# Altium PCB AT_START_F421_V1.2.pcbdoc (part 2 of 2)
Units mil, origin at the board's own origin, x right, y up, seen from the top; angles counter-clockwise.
Board outline 4706.37 x 3915.64 mil, 2 copper layers (Top Layer, Bottom Layer); 115 components, 101 nets, 469 pads, 319 vias.
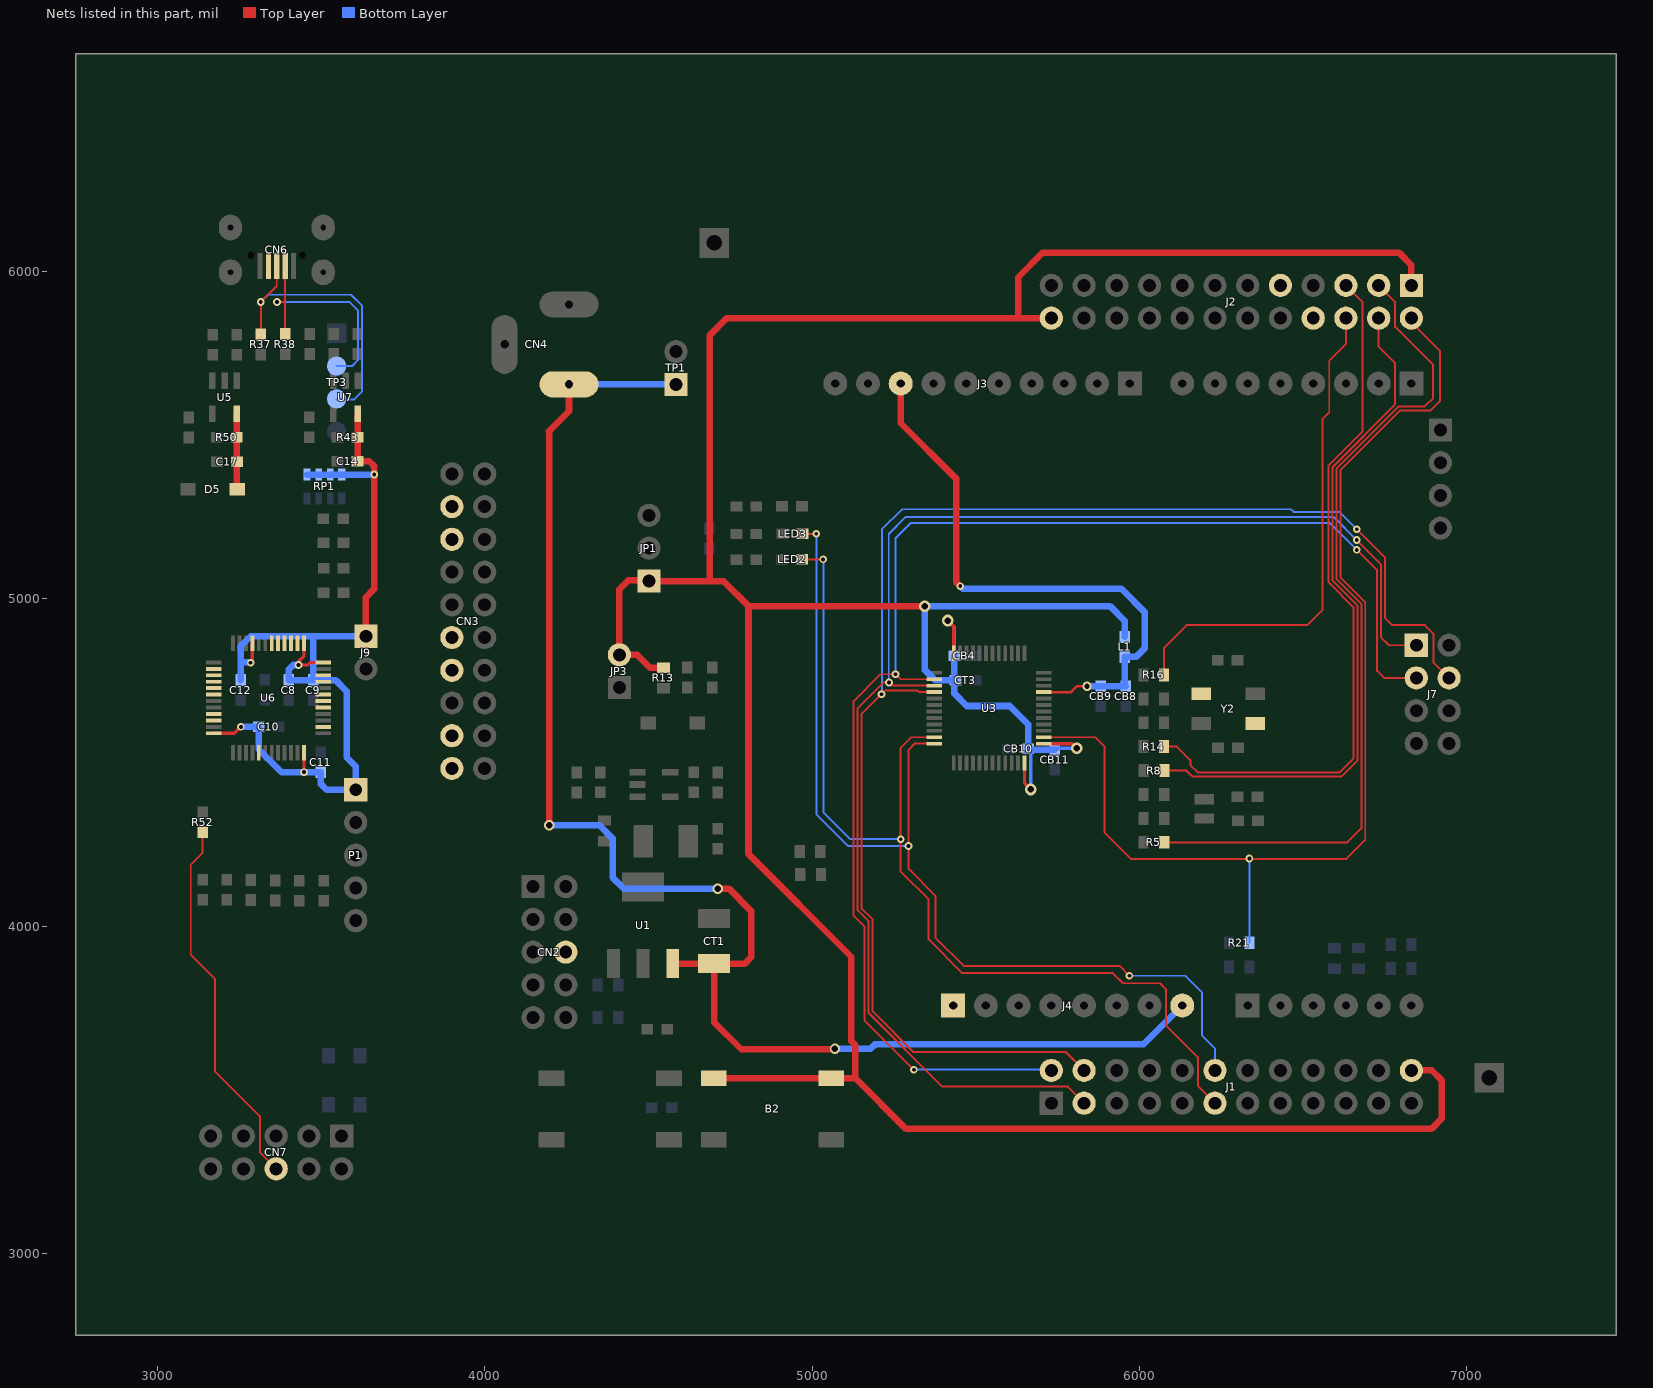
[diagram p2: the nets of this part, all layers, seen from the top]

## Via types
v1: diameter 23.62, hole 11.81, Top Layer to Bottom Layer, 298 vias
v2: diameter 35.43, hole 19.68, Top Layer to Bottom Layer, 11 vias
v3: diameter 31.5, hole 19.68, Top Layer to Bottom Layer, 8 vias
v4: diameter 27.56, hole 15.75, Top Layer to Bottom Layer, 2 vias

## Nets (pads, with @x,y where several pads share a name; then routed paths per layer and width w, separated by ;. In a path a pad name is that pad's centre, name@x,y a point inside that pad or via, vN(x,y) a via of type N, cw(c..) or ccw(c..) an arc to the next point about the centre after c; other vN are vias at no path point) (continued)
PB13: J1.2 J7.3 U3.26 | length 4312.9
  Top Layer w6: v1(5310.37,3561.94) 5160.37,3711.94 5160.37,3997.94 5126.37,4031.94 5126.37,4687.94 5208.37,4769.94 v1(5254.56,4769.94) 5269.86,4754.64 U3.26@5373.14,4754.64 ; v1(6663.37,5149.94) 6725.37,5087.94 6725.37,4780.09 6746.95,4758.51 J7.3@6845.37,4758.51
  Bottom Layer w6: v1(5254.56,4769.94) 5254.56,5186.13 5300.37,5231.94 6581.37,5231.94 v1(6663.37,5149.94) ; v1(5310.37,3561.94) 5728.8,3561.94 J1.2@5730.8,3559.94
PB14: J1.3 J7.1 U3.27 | length 4368.8
  Top Layer w6: U3.27@5373.14,4734.96 5244.35,4734.96 v1(5234.37,4744.94) 5217.94,4744.94 5138.37,4665.37 5138.37,4048.94 5172.37,4014.94 5172.37,3735.12 5397.55,3509.94 5780.8,3509.94 J1.3@5830.8,3459.94 ; v1(6663.37,5179.94) 6737.37,5105.94 6737.37,4883.09 6761.95,4858.51 J7.1@6845.37,4858.51
  Bottom Layer w6: v1(5234.37,4744.94) 5233.75,4745.56 5233.75,5198.32 5286.37,5250.94 6592.37,5250.94 v1(6663.37,5179.94)
PB15: J1.4 J7.4 U3.28 | length 4533.3
  Top Layer w6: U3.28@5373.14,4715.27 5327.04,4715.27 5321.37,4720.94 5223.37,4720.94 v1(5211.37,4708.94) 5150.37,4647.94 5150.37,4055.2 5184.37,4021.2 5184.37,3740.09 5308.52,3615.94 5774.8,3615.94 J1.4@5830.8,3559.94 ; v1(6663.37,5212.94) 6749.37,5126.94 6749.37,4943.09 6772.37,4920.09 6871.37,4920.09 6897.37,4894.09 6897.37,4806.51 J7.4@6945.37,4758.51
  Bottom Layer w6: v1(5211.37,4708.94) 5213.37,4710.94 5213.37,5110.89 5212.94,5111.32 5212.94,5212.51 5274.37,5273.94 6462.44,5273.94 6470.44,5265.94 6610.37,5265.94 v1(6663.37,5212.94)
PC13: J2.2 R21.2 U3.2 | length 3411.9
  Top Layer w6: U3.2@5707.79,4577.48 5864.37,4577.48 5892.37,4549.48 5892.37,4286.94 5973.37,4205.94 6631.22,4205.94 6689.37,4264.09 6689.37,4990 6613.37,5066 6613.37,5393.09 6796.37,5576.09 6889.37,5576.09 6917.37,5604.09 6917.37,5758.09 6829.95,5845.51 J2.2@6829.95,5857.24
  Bottom Layer w6: v1(6335.37,4206.94) 6335.84,4206.47 R21.2@6335.84,3949.86
PC14: J2.3 R5.2 | length 2547.6
  Top Layer w6: R5.2@6074.9,4256.58 6635.01,4256.58 6677.37,4298.94 6677.37,4985.03 6601.37,5061.03 6601.37,5398.06 6791.4,5588.09 6871.13,5588.09 6896.37,5613.34 6896.37,5714.94 6780.37,5830.94 6780.37,5906.81 J2.3@6729.95,5957.24
PC15: J2.4 R8.2 | length 2100.5
  Top Layer w6: R8.2@6074.9,4475.58 6143.33,4475.58 6161.02,4457.89 6617.32,4457.89 6665.37,4505.94 6665.37,4980.06 6589.37,5056.06 6589.37,5403.03 6780.37,5594.03 6780.37,5720.09 6729.95,5770.51 J2.4@6729.95,5857.24
PF0: J2.5 R14.2 | length 2178.9
  Top Layer w6: R14.2@6074.86,4548.79 6114.15,4548.79 6155.14,4507.8 6155.14,4492.17 6177.42,4469.89 6611.32,4469.89 6653.37,4511.94 6653.37,4975.09 6577.37,5051.09 6577.37,5408 6681.37,5512 6681.37,5905.81 J2.5@6629.95,5957.24
PF1: J2.6 R16.2 | length 1536.1
  Top Layer w6: R16.2@6074.43,4768.22 R16.2@6074.86,4767.79 6074.86,4851.42 6143.52,4920.09 6512.52,4920.09 6558.37,4965.94 6558.37,5549.09 6579.37,5570.09 6579.37,5727.51 6629.95,5778.09 J2.6@6629.95,5857.24
PF6: J1.11 LED2.2 U3.35 | length 3042.2
  Top Layer w6: LED2.2@4969.42,5120.5 4969.86,5120.94 v1(5033.37,5120.94) ; U3.35@5373.14,4577.48 5302.91,4577.48 5270.37,4544.94 v1(5270.37,4265.94) 5270.37,4166.94 5355.37,4081.94 5355.37,3959.94 5458.37,3856.94 5918.37,3856.94 5949.37,3825.94 6062.37,3825.94 6080.37,3807.94 6080.37,3697.7 6179.14,3598.94 6179.14,3511.6 J1.11@6230.8,3459.94
  Bottom Layer w6: v1(5033.37,5120.94) 5034.37,5119.94 5034.37,4347.94 5116.37,4265.94 v1(5270.37,4265.94)
PF7: J1.12 LED3.2 U3.36 | length 3054
  Top Layer w6: LED3.2@4970.57,5198.5 5011.93,5198.5 v1(5012.37,5198.94) ; U3.36@5373.14,4557.79 5373.14,4558.55 5313.99,4558.55 5294.37,4538.94 v1(5294.37,4244.94) 5294.37,4175.15 5376.37,4093.15 5376.37,3965.09 5462.52,3878.94 5938.79,3878.94 v1(5968.79,3848.94)
  Bottom Layer w6: v1(5012.37,5198.94) 5012.37,4342.94 5110.18,4245.13 5294.18,4245.13 v1(5294.37,4244.94) ; v1(5968.79,3848.94) 6139.37,3848.94 6190.37,3797.94 6190.37,3666.97 6230.8,3626.54 J1.12@6230.8,3559.94
SWO: CN7.6 R52.1 | length 1150.8
  Top Layer w6: R52.1@3137.55,4286.94 3137.55,4224.55 3101.61,4188.62 3101.61,3913.06 3175.55,3839.12 3175.55,3556.65 3312.43,3419.77 3312.43,3309.26 CN7.6@3362.55,3259.15
USBM: CN6.2 R38.1 TP3.2 | length 715.5
  Top Layer w6: v1(3365.13,5907.15) 3389.91,5907.15 ; R38.1@3389.4,5809.15 3389.91,5809.66 3389.91,5907.15 ; CN6.2@3390.06,6017.38 3389.91,6017.23 3389.91,5907.15
  Bottom Layer w6: v1(3365.13,5907.15) 3586.13,5907.15 3612.13,5881.15 3612.13,5729.15 3594.13,5711.15 TP3.2@3547.13,5711.15
USBP: CN6.3 R37.1 TP3.3 | length 910.9
  Top Layer w6: R37.1@3315.55,5808.04 v1(3315.55,5907.15) 3364.32,5955.92 3364.32,6017.23 CN6.3@3364.47,6017.38
  Bottom Layer w6: v1(3315.55,5907.15) 3337.55,5929.15 3591.13,5929.15 3625.13,5895.15 3625.13,5634.15 3602.13,5611.15 ; TP3.3@3547.13,5609.07 3602.13,5609.07
VCC: C8.2 C9.2 C10.2 C11.2 C12.2 C14.1 J9.1 P1.1 R43.2 RP1.5 RP1.6 RP1.7 RP1.8 U6.1 U6.9 U6.24 U6.36 U6.48 U7.5 | length 3028.5
  Top Layer w10: U6.24@3171.7,4589.56 3234.86,4589.56 v1(3254.55,4609.24) ; v1(3284.55,4805.15) 3289.81,4810.41 U6.9@3289.81,4865.15 ; v1@3447.29,4470.94 U6.36@3447.29,4530.5 ; U6.1@3447.29,4865.15 3447.29,4824.89 3430.55,4808.15 v1(3430.55,4798.15) 3459.55,4798.15 3467.49,4806.09 U6.48@3506.34,4806.09
  Top Layer w20: U7.5@3611.55,5565.96 3611.55,5421.25 C14.1@3611.17,5420.87 3647.06,5420.87 3661.55,5406.38 3661.55,5030.15 3636.55,5005.15 J9.1@3636.55,4886.15
  Bottom Layer w20: v1(3254.55,4609.24) C10.2@3309.49,4609.24 3309.49,4540.2 3378.93,4470.76 v1(3447.47,4470.76) C11.2@3499,4470.76 ; C12.2@3254.55,4752.15 3254.55,4806.15 ; v1(3284.55,4805.15) 3283.55,4806.15 3254.55,4806.15 ; v1(3430.55,4798.15) 3414.55,4798.15 3401.55,4785.15 C8.2@3401.55,4752.15 C9.2@3475.55,4752.15 ; RP1.8@3456.63,5379.86 RP1.7@3492.07,5379.86 RP1.6@3527.5,5379.86 RP1.5@3562.93,5379.86 v1(3662.07,5379.86) ; C11.2@3499.13,4470.89 3499.13,4434.65 3516.63,4417.15 P1.1@3605.55,4417.15 3605.55,4488.15 3577.55,4516.15 3577.55,4718.15 3543.55,4752.15 C9.2@3475.55,4752.15 ; J9.1@3636.55,4886.15 3475.55,4886.15 ; 3254.55,4806.15 3254.55,4856.15 3284.55,4886.15 3475.55,4886.15 ; C9.2@3475.55,4752.15 3475.55,4886.15
VCC3.5V: C17.1 D5.1 R50.2 U5.5 | length 231.2
  Top Layer w20: U5.5@3242.34,5566.04 3242.34,5335.93 D5.1@3243.13,5335.15
VDD: B2.1 CB4.1 CB10.1 CB11.1 CT3.1 J1.24 J2.1 J2.24 JP1.1 JP3.2 L1.1 R13.2 U3.1 U3.24 U3.48 | length 10805.7
  Top Layer w10: v2(5414.37,4933.94) 5432.2,4916.11 U3.24@5432.2,4833.38 ; U3.48@5648.73,4498.74 5648.73,4436.58 v2(5667.37,4417.94) ; U3.1@5707.79,4557.79 5794.52,4557.79 v2(5808.37,4543.94)
  Top Layer w20: JP1.1@4501.37,5055.09 JP1.1@4500.37,5054.09 ; 4504.01,4790.2 4464.97,4829.24 JP3.2@4410.97,4829.24 4410.97,5029.54 4438.37,5056.94 4466.52,5056.94 4469.37,5054.09 JP1.1@4500.37,5054.09 ; 4504.23,4789.98 R13.2@4545.69,4789.98 ; B2.1@4699.37,3535.9 B2.1@5058.37,3535.9 5132,3535.9 ; v2(5344.22,4978.09) 4805.37,4978.09 ; J2.24@5729.95,5857.24 5629.37,5857.24 ; J2.1@6829.95,5957.24 6829.95,6020.36 6792.37,6057.94 5704.37,6057.94 5629.37,5982.94 5629.37,5857.24 ; J1.24@6830.8,3559.94 6892.52,3559.94 6922.37,3530.09 6922.37,3412.09 6891.37,3381.09 5286.82,3381.09 5132,3535.9 ; JP1.1@4500.37,5054.09 4686.37,5054.09 ; 4686.37,5054.09 4729.37,5054.09 4805.37,4978.09 ; 4686.37,5054.09 4686.37,5805.09 4738.52,5857.24 5629.37,5857.24 ; 4805.37,4978.09 4805.37,4221.09 5119.37,3907.09 5119.37,3649.26 5132,3636.63 5132,3535.9
  Bottom Layer w10: v2(5414.37,4933.94) 5434.37,4913.94 CB4.1@5434.37,4826.94 ; v2(5667.37,4417.94) CB10.1@5667.37,4533.94 ; CB11.1@5741.37,4538.94 5746.37,4543.94 v2(5808.37,4543.94)
  Bottom Layer w20: CB4.1@5434.37,4826.94 CT3.1@5434.37,4751.94 ; CT3.1@5437.37,4751.94 CT3.1@5434.37,4751.94 ; CB11.1@5741.37,4538.94 5672.37,4538.94 5667.37,4533.94 CB10.1@5659.37,4541.94 5659.37,4616.94 5603.37,4672.94 5472.37,4672.94 5434.37,4710.94 CT3.1@5434.37,4751.94 ; L1.1@5954.37,4883.94 5954.37,4932.94 5909.22,4978.09 v2(5344.22,4978.09) 5344.22,4782.94 5375.22,4751.94 CT3.1@5434.37,4751.94
VDDA: CB8.1 CB9.1 J3.8 L1.2 U3.9 | length 1821.9
  Top Layer w8: U3.9@5707.79,4715.27 5791.05,4715.27 5809.02,4733.24 v4(5839.1,4733.24)
  Top Layer w20: J3.8@5270.37,5657.94 5270.37,5536.94 5439.37,5367.94 5439.37,5051.94 v1(5452.37,5038.94)
  Bottom Layer w20: v1(5452.37,5038.94) 5460.37,5030.94 5944.37,5030.94 6016.37,4958.94 6016.37,4849.94 5989.37,4822.94 L1.2@5954.37,4822.94 5954.37,4736.33 5957.42,4733.28 CB8.1@5957.26,4733.28 ; v4(5839.1,4733.24) 5881.6,4733.24 CB8.1@5957.46,4733.24
VIN: CN4.1 CT1.1 J4.8 TP1.1 U1.3 | length 4581.7
  Top Layer w20: v3(4197.08,4309.09) 4197.08,5510.69 4195.77,5512 4257.08,5573.3 CN4.1@4257.08,5655.42 ; U1.3@4573.92,3885.96 4700.25,3885.96 CT1.1@4700.37,3886.09 ; v3(4711.37,4115.09) 4745.37,4115.09 4813.37,4047.09 4813.37,3905.09 4794.37,3886.09 CT1.1@4700.37,3886.09 ; v3(5069.37,3626.09) 5067.37,3624.09 4783.37,3624.09 4700.37,3707.09 CT1.1@4700.37,3886.09
  Bottom Layer w20: v3(4197.08,4309.09) 4349.37,4309.09 4390.15,4268.31 4390.15,4149.31 4424.37,4115.09 v3(4711.37,4115.09) ; CN4.1@4257.08,5655.42 TP1.1@4583.83,5655.42 ; v3(5069.37,3626.09) 5178.37,3626.09 5191.37,3639.09 6011.52,3639.09 J4.8@6130.37,3757.94
"": CN2.6 CN3.3 CN3.5 CN3.11 CN3.13 CN3.17 CN3.19 CN6.4 CN6.MH1 CN6.MH2 J2.8 J2.9 J4.1 U6.2 U6.3 U6.4 U6.5 U6.6 U6.14 U6.15 U6.16 U6.17 U6.18 U6.21 U6.22 U6.29 U6.38 U6.41 U6.42 U6.43 U6.45 U6.46 Y2.2 Y2.4

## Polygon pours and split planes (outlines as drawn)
GND on Top Layer (solid, remove dead copper, pour order 0): 3747.58,3197.57 3078.19,3197.57 cw(c3078.19,3275.35) 3000.42,3275.35 3000.42,6136.49 cw(c3082.71,6136.49) 3082.71,6218.79 7127.67,6218.79 cw(c7127.67,6140.09) 7206.37,6140.09 7206.37,3271.1 cw(c7132.86,3271.1) 7132.86,3197.59
GND on Bottom Layer (solid, remove dead copper, pour order 1): 3747.58,3197.57 3078.19,3197.57 cw(c3078.19,3275.35) 3000.42,3275.35 3000.42,6136.49 cw(c3082.71,6136.49) 3082.71,6218.79 7127.67,6218.79 cw(c7127.67,6140.09) 7206.37,6140.09 7206.37,3271.1 cw(c7132.86,3271.1) 7132.86,3197.59

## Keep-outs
Board Outline Layer:
  circle w8 net "": c7082.37,6094.79 r62.99
  circle w8 net "": c7082.37,3320.1 r62.99
  circle w8 net "": c3891.39,6094.79 r62.99
  circle w8 net "": c3891.37,3320.1 r62.99
  circle w8 net "": c4880.37,3757.94 r62.99
  circle w8 net "": c6930.37,5057.94 r62.99
  circle w8 net "": c4930.37,5657.94 r62.99
  lines w8 net "": 3000.42,3275.35 3000,6160.4 cw(c3058.37,6160.41) 3058.37,6218.78 3082.71,6218.78 ; 3000.68,3275.35 ccw(c3079.42,3275.35) 3079.42,3196.61 ; 3649.37,6218.79 cw(c3649.37,6140.05) 3728.11,6140.05 3728.11,5823.39 ; 3649.76,3197.67 ccw(c3649.76,3276.41) 3728.5,3276.41 ; 3727.68,3726.18 3767.2,3726.18 ; 3727.68,3797.54 3767.2,3797.54 ; 3727.68,5094.61 3767.2,5094.61 ; 3727.81,3891.14 3767.33,3891.14 ; 3727.81,4000.62 3767.33,4000.62 ; 3727.81,5018.1 3767.33,5018.1 ; 3728.09,5746.33 3767.6,5746.33 ; 3728.37,3275.65 3728.37,3725.33 ; 3728.37,3798.39 3728.37,3890.39 ; 3728.37,4001.39 3728.37,5017.39 ; 3728.37,5095.39 3728.37,5745.39 ; 3728.94,5822.51 3768.46,5822.51 ; 3767.37,3275.59 3767.37,3725.33 ; 3767.33,3276.53 ccw(c3846.28,3276.53) 3846.28,3197.57 ; 3767.37,3798.39 3767.37,3890.39 ; 3767.37,4001.39 3767.37,5017.39 ; 3767.37,5095.39 3767.37,5745.39 ; 3767.63,5823.39 3767.63,6148.6 ; 3767.63,6140.05 cw(c3846.37,6140.05) 3846.37,6218.79 ; 7120.37,3197.59 7120.37,3000 6567.11,3000 3082.08,3000 3082.08,3197.59 6567.11,3197.59 7132.86,3197.59 ccw(c7132.86,3271.1) 7206.37,3271.1 ; 7120.37,6218.79 7120.37,6415.64 6566.21,6415.64 3082.71,6415.64 3082.71,6218.78 ; 7127.63,6218.79 6566.21,6218.79 3082.71,6218.79 ; 7127.63,6218.83 cw(c7127.63,6140.09) 7206.37,6140.09 7206.37,3269.94

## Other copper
Top Layer:
  drawing of 448 lines, arcs and shapes, not listed
Bottom Layer:
  region net $1N806: 3256.55,5651.15 3481.55,5651.15 3481.55,5683.15 3256.55,5683.15
  region net 3V3: 5520.37,3740.09 cw(c5420.37,3740.09) 5500.37,3680.09 5560.37,3680.09 cw(c5640.37,3740.09) 5540.37,3740.09
  region net ATLINK_5V: 3434.75,5879.15 3419.75,5849.15 ccw(c3419.75,5951.4) 3449.75,5853.65 3454.04,5874.65 ccw(c3434.75,5835.56)
  region net VCC: 3485.55,4816.15 cw(c3585.55,4816.15) 3505.55,4876.15 3445.55,4876.15 cw(c3365.55,4816.15) 3465.55,4816.15
  region net PB9: 6778.37,3674.39 6778.34,3673.63 6778.25,3672.82 6777.9,3671.07 6777.36,3669.22 6776.66,3667.34 6775.83,3665.52 6774.9,3663.83 6773.91,3662.35 6773.4,3661.71 6772.89,3661.15 6777.13,3656.91 6779.25,3663.27 6784.37,3674.39
  region net BOOT0: 4334.97,4024.2 4334.41,4024.23 4333.85,4024.33 4333.3,4024.5 4332.77,4024.72 4332.25,4024.99 4331.75,4025.31 4331.29,4025.67 4330.85,4026.07 4330.44,4026.51 4330.08,4026.98 4329.76,4027.48 4329.49,4028 4329.27,4028.53 4329.11,4029.08 4329.01,4029.64 4328.97,4030.2 4322.97,4030.2 4322.94,4029.64 4322.84,4029.08 4322.68,4028.53 4322.46,4028 4322.18,4027.48 4321.86,4026.98 4321.5,4026.51 4321.1,4026.07 4320.66,4025.67 4320.19,4025.31 4319.69,4024.99 4319.17,4024.72 4318.64,4024.5 4318.09,4024.33 4317.53,4024.23 4316.97,4024.2
  region net VDD: 5652.3,4534.87 5653.26,4533.83 5654.21,4532.64 5655.14,4531.31 5656.48,4529.13 5657.74,4526.75 5658.9,4524.23 5659.93,4521.64 5660.81,4519.03 5661.52,4516.46 5662.03,4514 5662.25,4512.44 5662.36,4510.97 5662.37,4510.28 5672.37,4510.28 5672.41,4511.37 5672.51,4512.44 5672.67,4513.47 5672.9,4514.48 5673.19,4515.45 5673.54,4516.39 5673.95,4517.31 5674.4,4518.19 5674.92,4519.03 5675.48,4519.85 5676.08,4520.63 5676.74,4521.38 5677.44,4522.1 5678.17,4522.78 5679.35,4523.74 5680.61,4524.63 5681.95,4525.43 5683.35,4526.15 5684.8,4526.8 5686.31,4527.36 5687.87,4527.84 5689.46,4528.23 5691.07,4528.54 5692.71,4528.76 5694.37,4528.89 5696.03,4528.94 5696.03,4548.94 5694.02,4548.87 5692.14,4548.69 5690.37,4548.41 5688.71,4548.05 5686.65,4547.48 5682.08,4545.9 5679.62,4545.06 5678.43,4544.74 5677.66,4544.57 5676.88,4544.44 5676.11,4544.37 5675.34,4544.35 5674.57,4544.4 5673.79,4544.51 5673,4544.7 5672.19,4544.96 5671.37,4545.31 5670.53,4545.75 5669.67,4546.29 5668.79,4546.93 5667.87,4547.68 5666.44,4549.01
  region net VDD: 5334.22,4958.09 5354.22,4948.09 ccw(c5286.06,4948.09) 5351.22,4968.09 5337.22,4970.95 ccw(c5363.28,4958.09)
  region net VDDA: 5480.37,5020.94 5484.51,5040.94 ccw(c5484.51,4991.27) 5467.51,5037.94 5467.51,5023.94 ccw(c5480.37,5050)
  region net 3V3: 3480,3742.94 3482.11,3742.87 3484.21,3742.68 3486.29,3742.36 3488.34,3741.92 3490.35,3741.35 3492.32,3740.68 3494.24,3739.88 3496.08,3738.98 3497.86,3737.97 3499.55,3736.86 3501.15,3735.65 3502.64,3734.34 3504.03,3732.93 3504.88,3731.94 3505.68,3730.91 3506.43,3729.84 3507.11,3728.74 3507.72,3727.6 3508.27,3726.42 3508.75,3725.2 3509.15,3723.96 3509.48,3722.67 3509.73,3721.36 3509.9,3720.01 3509.99,3718.64 3510,3717.94 3530,3717.94 3520,3747.94 3480,3772.94
  region net VDDA: 5911.26,4743.24 5911.26,4723.24 5941.26,4715.28 5941.26,4751.28
  region net VDDA: 5944.37,4781.28 5941.26,4751.28 5973.26,4751.28 5964.37,4781.28
  region net A5: 6843.84,3791.98 6797.5,3811.05 6791.88,3808.18 6794.91,3767.05
  region net A4: 6729.23,3794.54 6685.89,3801.81 6682.05,3797.17 6694.21,3752.23
  region net A3: 6632.67,3794.48 6588.48,3804.07 6584.24,3799.83 6593.83,3755.65
  region net A2: 6557.83,3782.16 6533.37,3820.18 6527.37,3820.18 6502.91,3782.16
  region net A1: 6466.92,3755.65 6476.51,3799.83 6472.27,3804.07 6428.08,3794.48
  region net A0: 6332.88,3803.55 6325.38,3794.55 6346.38,3794.55 6338.88,3803.55
  region net VIN: 4375.81,5665.42 4326.44,5690.42 4326.44,5620.42 4375.81,5645.42
  region net 3V3: 4025.95,5405.53 4009.37,5426.09 3989.37,5426.09 3972.8,5405.53
  region net PA13: 3897.15,5046.72 3939.84,5037.37 3944.09,5041.62 3934.74,5084.31
  region net PA14: 3897.15,4946.72 3939.84,4937.37 3944.09,4941.62 3934.74,4984.31
  region net NRST: 3897.15,4646.72 3939.84,4637.37 3944.09,4641.62 3934.74,4684.31
  region net PB13: 5708.81,3587.63 5670.37,3564.94 5669.95,3558.94 5705.17,3534.61
  region net PA15: 6333.57,3594.8 6290.66,3604.86 6286.3,3600.74 6294.96,3558.28
  region net PA14: 6333.19,3494.83 6290.36,3504.62 6286.05,3500.45 6294.98,3457.9
  region net PF7: 6257.23,3582.63 6233.8,3619.71 6227.8,3619.79 6204.08,3583.27
  region net PB8: 6765.73,3457.3 6775.09,3499.99 6770.84,3504.23 6728.15,3494.88
  region net PB9: 6757.23,3582.63 6733.8,3614.82 6727.8,3614.82 6704.08,3583.27
  region net PB2: 5895.01,5859.88 5885.66,5817.19 5889.9,5812.95 5932.59,5822.3
  region net A2: 6203.52,5834.55 6226.95,5808.52 6232.95,5808.52 6256.66,5833.91
  region net D0: 6265.74,5955.44 6275.09,5998.14 6270.84,6002.38 6228.15,5993.03
  region net A1: 6295.01,5959.88 6285.66,5917.19 6289.9,5912.95 6332.59,5922.3
  region net D1: 6327.55,5822.34 6370.38,5812.56 6374.7,5816.73 6365.77,5859.28
  region net D13: 6095.01,5959.88 6085.66,5917.19 6089.9,5912.95 6132.59,5922.3
  region net D12: 6096.99,5845.78 6095.09,5806.9 6101.15,5804.48 6146.33,5826.03
  region net D13: 5442.91,5633.72 5467.37,5608.94 5473.37,5608.94 5497.83,5633.72
  region net D13: 5497.83,5682.16 5473.37,5709.94 5467.37,5709.94 5442.91,5682.16
  region net D12: 5542.91,5633.72 5567.37,5595.69 5573.37,5595.69 5597.83,5633.72
  region net D12: 5597.83,5682.16 5573.37,5720.18 5567.37,5720.18 5542.91,5682.16
  region net D2: 6628.08,5621.4 6672.26,5611.8 6676.51,5616.05 6666.91,5660.23
  region net D1: 6757.83,5682.16 6733.37,5713.12 6727.37,5713.12 6702.91,5682.16
  region net D0: 6827.37,5703.55 6819.87,5694.55 6840.87,5694.55 6833.37,5703.55
  region net $3N595: 4597.93,3449.74 4588.93,3457.24 4588.93,3436.24 4597.93,3443.74
  region net $3N595: 4567.93,3470.09 4560.43,3461.09 4581.43,3461.09 4573.93,3470.09
  region net VDD: 5944.37,4931.94 5938.37,4901.94 5970.37,4901.94 5964.37,4931.94
  region net VDDA: 5944.37,4774.94 5964.37,4774.94 5970.37,4804.94 5938.37,4804.94
  region net VDDA: 5989.37,4832.94 5970.37,4840.94 5970.37,4804.94 5989.37,4812.94
  region net $2N484: 4524.05,5127.86 4561.52,5151.09 4561.69,5157.09 4525.55,5180.99
  region net 3V3: 6908.97,5581.52 6883.97,5551.52 6953.97,5551.52 6928.97,5581.52
  region net D2: 6895.53,5342.66 6858.73,5319.09 6858.73,5313.09 6895.53,5289.51
  region net 5V: 6943.15,4823.15 6980.9,4808.85 6995.04,4822.99 6980.74,4860.73
  region net NRST: 6810.01,4660.73 6800.66,4618.04 6804.9,4613.8 6847.59,4623.15
  region net ATLK_RX: 4211.82,3723.42 4202.47,3680.73 4206.71,3676.49 4249.41,3685.84
  region net ATLK_RX: 4270.88,3694.86 4307.45,3718.55 4307.39,3724.55 4270.36,3748
  region net ATLK_TX: 4211.82,3823.42 4202.47,3780.73 4206.71,3776.49 4249.41,3785.84
  region net ATLK_TX: 4270.55,3794.56 4307.41,3818.1 4307.43,3824.1 4270.7,3847.71
  region net NRST: 4123.75,3847.77 4086.95,3824.2 4086.95,3818.2 4123.75,3794.63
  region net PA14: 4144.97,3885.84 4187.66,3876.49 4191.9,3880.73 4182.55,3923.42
  region net PA14: 4123.75,3947.77 4086.95,3924.2 4086.95,3918.2 4123.75,3894.63
  region net BOOT0: 4270.62,3994.63 4307.42,4018.2 4307.42,4024.2 4270.62,4047.77
  region net PA13: 4144.97,3985.84 4187.66,3976.49 4191.9,3980.73 4182.55,4023.42
  region net PA13: 4123.75,4047.77 4086.95,4024.2 4086.95,4018.2 4123.75,3994.63
  region net 5V: 4273.76,4144.64 4257.19,4167.57 4237.19,4167.57 4220.61,4144.64
  region net $2N484: 4660.88,5157.09 4660.88,5151.09 4669.88,5143.59 4669.88,5164.59
  region net BOOT0: 4660.88,5218.05 4660.88,5212.05 4669.88,5204.55 4669.88,5225.55
  region net VCC: 3447.55,4762.15 3417.55,4770.15 3417.55,4734.15 3447.55,4742.15
  region net VCC: 3391.55,4785.15 3385.55,4770.15 3417.55,4770.15 3411.55,4785.15
  region net VCC: 3429.55,4762.15 3429.55,4742.15 3459.55,4734.15 3459.55,4770.15
  region net VCC: 3465.55,4800.15 3459.55,4770.15 3491.55,4770.15 3485.55,4800.15
  region net VCC: 3521.55,4762.15 3491.55,4770.15 3491.55,4734.15 3521.55,4742.15
  region net VCC: 3299.49,4563.24 3319.49,4563.24 3327.49,4593.24 3291.49,4593.24
  region net VCC: 3261.49,4619.24 3261.49,4599.24 3291.49,4593.24 3291.49,4625.24
  region net VCC: 3453.13,4480.76 3453.13,4460.76 3483.13,4452.89 3483.13,4488.89
  region net VCC: 3489.13,4434.65 3509.13,4434.65 3515.13,4452.89 3483.13,4452.89
  region net VCC: 3244.55,4800.15 3238.55,4770.15 3270.55,4770.15 3264.55,4800.15
  region net ATLK_TX: 3297.91,3256.93 3307.26,3299.62 3303.02,3303.86 3260.33,3294.51
  region net NRST: 3289.12,3382.58 3265.55,3419.38 3259.55,3419.38 3235.97,3382.58
  region net ATLINK_5V: 3585.98,3232.57 3615.85,3244.15 3615.85,3274.15 3585.98,3285.72
  region net 3V3: 3562.65,3424.58 3537.65,3394.58 3597.98,3394.58 3582.65,3424.58
  region net 3V3: 3512.07,3551.24 3532.07,3551.24 3541.75,3581.24 3502.38,3581.24
  region net 3V3: 3510,3658.48 3502.38,3628.48 3541.75,3628.48 3530,3658.48
  region net VCC: 3571.11,4896.15 3571.11,4876.15 3601.11,4851.15 3601.11,4921.15
  region net M-NRST: 3640.91,4114.93 3650.26,4157.62 3646.02,4161.86 3603.33,4152.51
  region net VCC: 3540.11,4427.15 3540.11,4407.15 3570.11,4382.15 3570.11,4452.15
  region net VCC: 3595.55,4482.58 3570.55,4452.58 3640.55,4452.58 3615.55,4482.58
  region net VCC: 3492.07,5389.86 3467.46,5398.56 3467.46,5361.16 3492.07,5369.86
  region net VCC: 3456.63,5389.86 3456.63,5369.86 3482.23,5361.16 3482.23,5398.56
  region net VCC: 3527.5,5389.86 3501.91,5398.56 3501.91,5361.16 3527.5,5369.86
  region net VCC: 3492.07,5389.86 3492.07,5369.86 3517.66,5361.16 3517.66,5398.56
  region net VCC: 3562.93,5389.86 3537.34,5398.56 3537.34,5361.16 3562.93,5369.86
  region net VCC: 3603.76,5389.86 3573.76,5398.56 3573.76,5361.16 3603.76,5369.86
  region net VCC: 3527.5,5389.86 3527.5,5369.86 3552.11,5361.16 3552.11,5398.56
  region net $1N792: 3453.63,5279.33 3459.63,5279.33 3467.13,5288.33 3446.13,5288.33
  region net $1N793: 3489.07,5279.33 3495.07,5279.33 3501.91,5288.33 3482.23,5288.33
  region net $1N794: 3524.5,5279.33 3530.5,5279.33 3537.34,5288.33 3517.66,5288.33
  region net $1N795: 3559.93,5279.33 3565.93,5279.33 3573.43,5288.33 3552.43,5288.33
  region net USBP: 3565.05,5587.68 3597.09,5606.07 3597.51,5612.07 3568.16,5631.87
  region net USBM: 3566.66,5689 3594.13,5708.15 3594.13,5714.15 3566.66,5733.29
  region net ATLINK_5V: 3484.13,5826.15 3484.13,5796.15 3517.6,5781.62 3517.6,5840.67
  region net M-NRST: 3325.05,4780.19 3317.55,4771.19 3338.55,4771.19 3331.05,4780.19
  region net 5V: 3613.16,3657.82 3598.86,3627.82 3638.23,3627.82 3633.16,3657.82
  region net ATLINK_5V: 3670.05,3423.91 3638.23,3477.82 3638.23,3430.58 3652.77,3398.76
  region net VDDA: 5839.1,4743.24 5839.1,4723.24 5865.6,4715.28 5865.6,4751.28
  region net VDDA: 5927.6,4743.24 5897.6,4751.28 5897.6,4715.28 5927.6,4723.24
  region net VDD: 5662.37,4510.94 5672.37,4510.94 5677.37,4525.94 5649.87,4525.94
  region net VDD: 5707.37,4548.94 5677.37,4557.94 5677.37,4525.94 5707.37,4528.94
  region net VDD: 5649.37,4587.94 5641.37,4557.94 5677.37,4557.94 5669.37,4587.94
  region net VDD: 5695.37,4548.94 5695.37,4528.94 5725.37,4520.94 5725.37,4556.94
  region net VDD: 5772.37,4548.94 5757.37,4556.94 5757.37,4526.44 5772.37,4538.94
  region net VDD: 5424.37,4710.94 5444.37,4710.94 5455.37,4735.94 5419.37,4735.94
  region net VDD: 5389.37,4761.94 5389.37,4741.94 5419.37,4735.94 5419.37,4767.94
  region net VDD: 5424.37,4797.94 5419.37,4767.94 5455.37,4767.94 5444.37,4797.94
  region net VDD: 5424.37,4780.94 5444.37,4780.94 5452.37,4810.94 5416.37,4810.94
  region net VDD: 5429.37,4857.94 5416.87,4842.94 5451.87,4842.94 5439.37,4857.94
  region net VIN: 4518.4,5665.42 4518.4,5645.42 4548.4,5620.42 4548.4,5690.42
  region net VIN: 6093.83,3760.23 6079.29,3721 6093.43,3706.85 6132.67,3721.4
  region net 5V: 5857.83,3782.16 5840.37,3809.94 5820.37,3809.94 5802.91,3782.16
  region net 3V3: 5702.91,3733.72 5720.37,3704.09 5740.37,3704.09 5757.83,3733.72
  region net 3V3: 5502.91,3733.72 5520.37,3695.69 5540.37,3695.69 5557.83,3733.72
  region net $3N595: 4625.28,3455.59 4613.02,3449.74 4613.02,3443.74 4625.28,3437.88
  region net 5V: 4290.41,4337.21 4306.76,4339.02 4306.76,4359.02 4290.41,4360.83
  region net 5V: 4748.19,4163.67 4731.83,4161.85 4731.83,4141.85 4748.19,4140.04
  region net NRST: 4574.16,3768.11 4578.69,3780.92 4574.45,3785.17 4561.63,3780.64
  region net VIN: 4700.96,4126.9 4684.6,4125.09 4684.6,4105.09 4700.96,4103.28
  region net VIN: 4207.49,4297.28 4223.85,4299.09 4223.85,4319.09 4207.49,4320.9
  region net VIN: 5079.79,3614.28 5096.14,3616.09 5096.14,3636.09 5079.79,3637.9
  region net 3V3: 5074.2,3659.05 5090.83,3660.09 5093.39,3680.09 5077.2,3682.48
  region net PA15: 6036.18,3890.23 6048.45,3896.09 6048.45,3902.09 6036.18,3907.95
  region net 3V3: 3506.71,3746.67 3510,3728.27 3530,3728.27 3533.29,3746.67
  region net $1N795: 3463.88,5009.29 3476.15,5015.15 3476.15,5021.15 3463.88,5027
  region net $1N794: 3463.88,5085 3476.15,5090.86 3476.15,5096.86 3463.88,5102.72
  region net $1N793: 3463.88,5162.19 3476.15,5168.05 3476.15,5174.05 3463.88,5179.91
  region net $1N792: 3465.63,5253.28 3459.63,5265.33 3453.63,5265.11 3447.93,5252.63
  region net M-NRST: 3333.88,4941 3346.15,4946.86 3346.15,4952.86 3333.88,4958.72
  region net M-NRST: 3319.44,4800.87 3325.05,4788.25 3331.05,4787.9 3337.13,4799.83
  region net M-USB_DM: 3350.73,4445 3338.47,4439.15 3338.47,4433.15 3350.73,4427.29
  region net M-USB_DP: 3350.73,4402 3338.47,4396.15 3338.47,4390.15 3350.73,4384.29
  region net USBP: 3327.33,5906.41 3331.87,5919.22 3327.62,5923.47 3314.81,5918.93
  region net USBM: 3372.94,5898.29 3385.2,5904.15 3385.2,5910.15 3372.94,5916
  region net M-USB_DM: 3355.34,5460.89 3350.81,5448.07 3355.05,5443.83 3367.87,5448.36
  region net M-USB_DP: 3322.34,5460.89 3317.81,5448.07 3322.05,5443.83 3334.87,5448.36
  region net VDDA: 5848.21,4722.91 5862.52,4723.24 5862.52,4743.24 5848.21,4743.58
  region net PB13: 5318.18,3553.08 5330.45,3558.94 5330.45,3564.94 5318.18,3570.8
  region net D8: 5223.11,3953.73 5210.29,3958.26 5206.05,3954.02 5210.58,3941.2
  region net PB9: 6649.88,3990.13 6655.74,3977.86 6661.74,3977.86 6667.59,3990.13
  region net $3N595: 6263.92,4032.84 6269.91,4020.77 6275.91,4020.96 6281.63,4033.42
  region net $3N595: 5834.5,4054.1 5840.37,4041.85 5846.37,4041.87 5852.22,4054.16
  region net PC13: 6326.83,4198.78 6332.84,4186.74 6338.84,4186.98 6344.53,4199.48
  region net A1: 6288.23,5599.75 6282.37,5612.02 6276.37,5612.02 6270.51,5599.75
  region net PB12: 5284.23,4803.75 5278.37,4816.02 5272.37,4816.02 5266.51,4803.75
  region net PB13: 5263.42,4777.75 5257.56,4790.02 5251.56,4790.02 5245.7,4777.75
  region net PB14: 5242.81,4753.21 5236.75,4765.17 5230.75,4764.85 5225.11,4752.27
  region net PB15: 5221.42,4715.14 5216.37,4728.45 5210.37,4729.48 5203.96,4718.14
  region net D2: 5251.56,4661.8 5239.29,4655.94 5239.29,4649.94 5251.56,4644.08
  region net PB6: 5076.63,4216.15 5089.45,4211.62 5093.69,4215.86 5089.16,4228.68
  region net PB6: 5527.56,4219.8 5515.29,4213.94 5515.29,4207.94 5527.56,4202.08
  region net D8: 5212.11,4646.73 5199.29,4651.26 5195.05,4647.02 5199.58,4634.2
  region net D5: 5463.56,4354.95 5451.29,4349.09 5451.29,4343.09 5463.56,4337.23
  region net A2: 6189.23,5593.75 6183.37,5606.02 6177.37,5606.02 6171.51,5593.75
  region net A3: 6030.56,5469 6018.29,5463.15 6018.29,5457.15 6030.56,5451.29
  region net A3: 6047.94,5453.23 6059.05,5459.75 6057.69,5465.75 6044.04,5470.51
  region net A2: 6168.8,5448.86 6157.7,5442.34 6159.05,5436.34 6172.7,5431.58
  region net A2: 6186.18,5433.08 6198.45,5438.94 6198.45,5444.94 6186.18,5450.8
  region net A1: 6287.18,5410.08 6299.45,5415.94 6299.45,5421.94 6287.18,5427.8
  region net PB9: 5616.47,4316.71 5604.26,4310.87 5604.32,4304.87 5616.65,4299
  region net PB9: 5616.56,4316.8 5604.29,4310.94 5604.29,4304.94 5616.56,4299.08
  region net D9: 5537.56,4340.8 5525.29,4334.94 5525.29,4328.94 5537.56,4323.08
  region net PB8: 5097.58,5407.68 5093.05,5394.86 5097.29,5390.62 5110.11,5395.15
  region net PB9: 5133.58,5409.68 5129.05,5396.86 5133.29,5392.62 5146.11,5397.15
  region net D5: 6320.87,5399.49 6309.44,5393.13 6310.37,5387.13 6323.59,5381.99
  region net D4: 6422.7,5379.92 6410.34,5374.13 6410.25,5368.13 6422.42,5362.21
  region net D3: 6519.29,5359.49 6507.87,5353.13 6508.8,5347.13 6522.01,5341.99
  region net D8: 6013.37,5344.8 6001.1,5338.94 6001.1,5332.94 6013.37,5327.08
  region net D8: 6024.71,5324.67 6039.68,5328.13 6042.36,5334.13 6031.93,5340.85
  region net D8: 6623.58,5359.68 6619.05,5346.86 6623.29,5342.62 6636.11,5347.15
  region net D2: 6665.17,5323.35 6653.83,5316.94 6654.86,5310.94 6668.17,5305.89
  region net NRST: 6485.18,5284.08 6497.45,5289.94 6497.45,5295.94 6485.18,5301.8
  region net NRST: 6645.11,5277.73 6632.29,5282.26 6628.05,5278.02 6632.58,5265.2
  region net PB15: 6664.11,5224.73 6651.29,5229.26 6647.05,5225.02 6651.58,5212.2
  region net PB14: 6664.11,5191.73 6651.29,5196.26 6647.05,5192.02 6651.58,5179.2
  region net PB12: 6665.11,5127.73 6652.29,5132.26 6648.05,5128.02 6652.58,5115.2
  region net PB11: 5528.84,5191.1 5517.05,5184.94 5517.56,5178.94 5530.34,5173.45
  region net PB11: 5545.18,5174.08 5557.45,5179.94 5557.45,5185.94 5545.18,5191.8
  region net A3: 5650.75,5452 5663.95,5457.15 5664.87,5463.15 5653.44,5469.51
  region net A2: 5799.18,5430.08 5811.45,5435.94 5811.45,5441.94 5799.18,5447.8
  region net PB11: 6664.11,5093.73 6651.29,5098.26 6647.05,5094.02 6651.58,5081.2
  region net D7: 6118.58,5160.68 6114.05,5147.86 6118.29,5143.62 6131.11,5148.15
  region net A0: 6388.18,5016.08 6400.45,5021.94 6400.45,5027.94 6388.18,5033.8
  region net PB2: 5455.11,5573.73 5442.3,5578.26 5438.05,5574.02 5442.58,5561.2
  region net D9: 5840.56,5419.8 5828.29,5413.94 5828.29,5407.94 5840.56,5402.08
  region net D10: 5763.56,5502.8 5751.29,5496.94 5751.29,5490.94 5763.56,5485.08
  region net D13: 5724.34,5530.43 5711.56,5524.94 5711.05,5518.94 5722.84,5512.77
  region net D12: 5689.56,5554.8 5677.29,5548.94 5677.29,5542.94 5689.56,5537.08
  region net D12: 5705.18,5537.08 5717.45,5542.94 5717.45,5548.94 5705.18,5554.8
  region net PB1: 5628.18,5580.08 5640.45,5585.94 5640.45,5591.94 5628.18,5597.8
  region net NRST: 6789.23,4122.75 6783.37,4135.02 6777.37,4135.02 6771.51,4122.75
  region net NRST: 5868.21,4106.4 5874.37,4094.62 5880.37,4095.13 5885.86,4107.91
  region net PA14: 6002.84,3860.74 6015.98,3865.94 6016.85,3871.94 6005.37,3878.28
  region net PF7: 5976.6,3840.08 5988.87,3845.94 5988.87,3851.94 5976.6,3857.8
  region net PA15: 5415.56,4167.8 5403.29,4161.94 5403.29,4155.94 5415.56,4150.08
  region net PA15: 5086.91,4149.77 5098.69,4155.94 5098.18,4161.94 5085.41,4167.43
  region net PA13: 5296.56,4015.8 5284.29,4009.94 5284.29,4003.94 5296.56,3998.08
  region net PA14: 5393.36,3992.35 5382.02,3985.94 5383.05,3979.94 5396.36,3974.89
  region net D2: 5246.11,3979.73 5237.35,3980.2 5233.11,3975.96 5233.58,3967.2
  region net NRST: 5371.56,3901.8 5359.29,3895.94 5359.29,3889.94 5371.56,3884.08
  region net NRST: 5387.18,3884.08 5399.45,3889.94 5399.45,3895.94 5387.18,3901.8
  region net 5V: 5011.79,3841.96 5012.37,3825.19 5032.37,3821.31 5034.98,3837.46
  region net 5V: 5036.52,3838.81 5052.77,3840.94 5051.5,3860.94 5035.02,3862.39
  region net PF6: 5262.56,4274.8 5250.29,4268.94 5250.29,4262.94 5262.56,4257.08
  region net PF7: 5286.7,4253.92 5274.34,4248.13 5274.25,4242.13 5286.42,4236.21
  region net D10: 5065.04,4365.56 5059.18,4377.83 5053.18,4377.83 5047.32,4365.56
  region net PF6: 5025.21,5112.4 5031.37,5100.62 5037.37,5101.13 5042.86,5113.9
  region net PF7: 5003.51,5191.13 5009.37,5178.86 5015.37,5178.86 5021.23,5191.13
  region net VDD: 5330.93,4966.37 5334.22,4947.97 5354.22,4947.97 5357.51,4966.37
  region net VDD: 5355.94,4964.8 5374.34,4968.09 5374.34,4988.09 5355.94,4991.38
  region net VDD: 5413.26,4916.26 5430.84,4910.4 5437.91,4917.47 5432.05,4935.05
  region net VDD: 5680.66,4429.66 5672.37,4448.06 5662.37,4448.06 5654.08,4429.66
  region net VDD: 5796.65,4557.23 5778.25,4548.94 5778.25,4538.94 5796.65,4530.65
  region net PB11: 5382.07,5173.13 5394.41,5178.94 5394.49,5184.94 5382.29,5190.85
  region net BOOT0: 5578.56,4055.8 5566.29,4049.94 5566.29,4043.94 5578.56,4038.08
  region net LD4: 3149.32,4529.73 3136.5,4534.26 3132.26,4530.02 3136.79,4517.2
  region net LD4: 3119.69,4908.48 3125.55,4896.21 3131.55,4896.21 3137.4,4908.48
  region net ATLK_RX: 3461.56,3819.8 3449.29,3813.94 3449.29,3807.94 3461.56,3802.08
  region net ATLK_RX: 3477.18,3802.08 3489.45,3807.94 3489.45,3813.94 3477.18,3819.8
  region net NRST: 3320.36,3855.08 3332.63,3860.94 3332.63,3866.94 3320.36,3872.8
  region net BOOT0: 3293.36,3909.08 3305.63,3914.94 3305.63,3920.94 3293.36,3926.8
  region net D3: 5494.76,4406.8 5482.49,4400.94 5482.49,4394.94 5494.76,4389.08
  region net D4: 5439.26,4381.8 5426.99,4375.94 5426.99,4369.94 5439.26,4364.08
  region net D7: 5488.18,5133.08 5500.45,5138.94 5500.45,5144.94 5488.18,5150.8
  region net D6: 6218.58,5124.68 6218.25,5116.06 6222.49,5111.82 6231.11,5112.15
  region net D6: 5311.23,4703.4 5305.37,4715.67 5299.37,4715.67 5293.51,4703.4
  region net PB8: 5602.11,4281.73 5589.29,4286.26 5585.05,4282.02 5589.58,4269.2
  region net PA13: 3685.43,3872.41 3672.62,3876.94 3668.37,3872.69 3672.91,3859.88
  region net NRST: 3303.64,3618.28 3309.5,3606.01 3315.5,3606.01 3321.36,3618.28
  region net ATLK_RX: 3156.19,3802.17 3168.59,3807.94 3168.72,3813.94 3156.58,3819.88
  region net PA13: 3244.9,3941.48 3257.17,3947.34 3257.17,3953.34 3244.9,3959.2
  region net PA14: 3206.88,3884.08 3219.15,3889.94 3219.15,3895.94 3206.88,3901.8
  region net ATLK_TX: 3340,3618.28 3345.86,3606.01 3351.86,3606.01 3357.72,3618.28
  region net ATLK_TX: 3358.39,3828.09 3370.66,3833.94 3370.66,3839.94 3358.39,3845.8
  region net PA14: 3635.29,3815.73 3622.47,3820.26 3618.23,3816.02 3622.76,3803.2
  region net BOOT0: 3658.96,3841.88 3646.14,3846.41 3641.9,3842.17 3646.43,3829.35
  region net 5V: 4076.98,4178.61 4087.26,4191.45 4073.12,4205.59 4060.27,4195.31
  region net 5V: 3609.87,3708.75 3613.16,3690.35 3633.16,3690.35 3636.44,3708.75

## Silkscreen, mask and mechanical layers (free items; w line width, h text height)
Top Silkscreen Layer:
  drawing of 1269 lines, arcs and shapes, not listed
  text "23" at 5697.37,6122.94 h36
  text "11" at 6306.37,6122.09 h36
  text "1" at 6822.37,6122.09 h36
  text "B1" at 5925.37,6032.98 h40 r45
  text "A1" at 6324.79,6031.5 h40 r45
  text "F0" at 6619.13,6029.14 h40 r45
  text "NC" at 6422.07,6025.5 h40 r45
  text "A7" at 6017.43,6025.44 h40 r45
  text "A5" at 6124.06,6025.44 h40 r45
  text "A3" at 6222.62,6025.44 h40 r45
  text "NRST" at 6515.39,6025.44 h40 r45
  text "B10" at 5811.65,6018.54 h36 r45
  text "GND" at 5707.41,6016.42 h36 r45
  text "C14" at 6704.68,6014.4 h40 r45
  text "VDD" at 6801.68,6014.33 h40 r45
  text "GND" at 4647.6,5944.61 h48
  text "F1" at 6623.82,5725.19 h40 r45
  text "B2" at 5913.35,5716.91 h40 r45
  text "B0" at 6014.38,5716.91 h40 r45
  text "A6" at 6116.33,5716.1 h40 r45
  text "A4" at 6220.93,5714.75 h40 r45
  text "A2" at 6318.56,5715.42 h40 r45
  text "A0" at 6416.06,5715.42 h40 r45
  text "NC" at 6515.39,5715.49 h40 r45
  text "B11" at 5806.41,5712.6 h40 r45
  text "C15" at 6717.75,5707.46 h38 r45
  text "C13" at 6820.04,5707.46 h38 r45
  text "VDD" at 5696.19,5704.32 h40 r45
  text "VIN (7V-12V)" at 4513.05,5659.05 h48 r90
  text "4" at 6455.67,5548.09 h48 r90
  text "8" at 5994.67,5547.09 h48 r90
  text "7" at 6158.67,5547.09 h48 r90
  text "2" at 6652.67,5547.09 h48 r90
  text "13" at 5492.67,5506.09 h48 r90
  text "12" at 5592.67,5506.09 h48 r90
  text "#6" at 6254.67,5500.09 h48 r90
  text "#5" at 6355.67,5500.09 h48 r90
  text "#9" at 5893.67,5499.09 h48 r90
  text "#3" at 6554.67,5499.09 h48 r90
  text "#11" at 5692.67,5459.09 h48 r90
  text "#10" at 5793.67,5459.09 h48 r90
  text "SCL" at 5092.67,5449.09 h48 r90
  text "SDA" at 5192.67,5449.09 h48 r90
  text "GND" at 5393.37,5449.09 h48 r90
  text "DIGITAL(#=PWM)" at 5842.67,5405.09 h48
  text "TX 1" at 6755.67,5404.09 h48 r90
  text "RX 0" at 6856.67,5404.09 h48 r90
  text "VDDA" at 5293.37,5402.09 h48 r90
  text "LD:" at 3643.7,5363.05 h36 r270
  text "BOOT0" at 4398.37,5331.94 h48
  text "AT-Link-EZ V1.4" at 3044.13,5261.15 h60 r270
  text "1" at 3645.87,5246.75 h36 r270
  text "GND" at 4420.37,5208.73 h36 r90
  text "2" at 3644.87,5179.75 h36 r270
  text "3" at 3643.87,5106.75 h36 r270
  text "AT-START-F421 V1.2" at 5495.03,5091.94 h59.06
  text "4" at 3644.87,5031.75 h36 r270
  text "VDD" at 4420.37,5003.05 h36 r90
  text "MISO" at 6606.56,4837.17 h48
  text "5V" at 7020.08,4836.2 h48
  text "SCK" at 6647.23,4736.13 h48
  text "MOSI" at 7020.62,4735.99 h48
  text "IDD" at 4332.44,4721.13 h48 r90
  text "RESET" at 6551.01,4636.84 h48
  text "GND" at 7020.08,4635.77 h48
  text "NSS" at 6646.8,4536.68 h48
  text "PB11" at 7020.08,4536.1 h48
  text "20-pin ARM standard JTAG" at 4203.32,4371.09 h48 r90
  text "POWER" at 5933.24,3986.71 h48
  text "ANALOG IN" at 6449.39,3986.26 h48
  text "IOREF" at 5555.37,3832.94 h48 r90
  text "RESET" at 5655.37,3832.94 h48 r90
  text "3.3V" at 5753.37,3833.09 h48 r90
  text "5V" at 5853.37,3833.09 h48 r90
  text "VIN" at 6157.37,3832.94 h48 r90
  text "AN0" at 6350.37,3832.94 h48 r90
  text "AN1" at 6450.37,3832.94 h48 r90
  text "AN2" at 6551.37,3833.09 h48 r90
  text "AN3" at 6650.37,3832.94 h48 r90
  text "AN4" at 6750.37,3832.94 h48 r90
  text "AN5" at 6850.37,3832.94 h48 r90
  text "GND" at 5960.37,3825.94 h48 r90
  text "GND" at 6062.37,3825.94 h48 r90
  text "SWC" at 3336.69,3777.95 h42 r270
  text "GND" at 3145.37,3776.94 h42 r270
  text "SWD" at 3435.3,3776.8 h42 r270
  text "3V3" at 3541.93,3775.79 h42 r270
  text "NRST" at 3243.37,3773.94 h42 r270
  text "AT-Link" at 4024.47,3754.81 h48 r90
  text "GND" at 7008.14,3633.16 h48
  text "F7" at 6221.28,3628.57 h40 r45
  text "B6" at 6513.8,3627.02 h40 r45
  text "B9" at 6730.37,3627.02 h40 r45
  text "A9" at 5912.13,3625.54 h40 r45
  text "B4" at 6412.37,3625.67 h40 r45
  text "A11" at 6007.28,3620.55 h40 r45
  text "B13" at 5699.04,3619.98 h38 r40
  text "B15" at 5804.89,3619.98 h38 r40
  text "A13" at 6101.92,3618.7 h38 r40
  text "A15" at 6295.25,3618.7 h38 r40
  text "BOOT0" at 6577.21,3617.02 h30 r30
  text "VDD" at 6818.88,3613.75 h40 r45
  text "SWO" at 3342.42,3602.51 h42 r270
  text "BOOT0" at 3441.52,3602.51 h40 r270
  text "RX" at 3144.49,3601.53 h42 r270
  text "5V" at 3539.88,3600.55 h42 r270
  text "TX" at 3231.04,3599.56 h42 r270
  text "F6" at 6229.42,3315.08 h40 r45
  text "B3" at 6418.27,3312.19 h40 r45
  text "B5" at 6517.63,3312.19 h40 r45
  text "B7" at 6628.68,3312.19 h40 r45
  text "B8" at 6727.2,3312.19 h40 r45
  text "A8" at 5919.67,3310.7 h40 r45
  text "B12" at 5696.83,3301.82 h40 r45
  text "B14" at 5812.83,3301.14 h40 r45
  text "A10" at 6008.2,3300.34 h40 r45
  text "A12" at 6104.59,3300.34 h40 r45
  text "A14" at 6306.91,3299.66 h40 r45
  text "GND" at 6829.9,3298.11 h40 r45
  text "25" at 5688.37,3239.09 h36
  text "35" at 6200.37,3239.09 h36
  text "48" at 6797.37,3239.09 h36
  text "RESET" at 4268.17,3229.9 h48
  text "USER" at 4789.26,3229.9 h48
Bottom Silkscreen Layer:
  drawing of 295 lines, arcs and shapes, not listed
  text "23" at 5716.85,6029.09 h36 r315
  text "21" at 5816.85,6029.09 h36 r315
  text "19" at 5921.85,6029.09 h36 r315
  text "17" at 6012.85,6029.09 h36 r315
  text "15" at 6114.85,6029.09 h36 r315
  text "13" at 6221.85,6029.09 h36 r315
  text "NC" at 6410.85,6029.09 h36 r315
  text "7" at 6515.27,6029.09 h36 r315
  text "5" at 6614.27,6029.09 h36 r315
  text "3" at 6713.27,6029.09 h36 r315
  text "1" at 6808.27,6029.09 h36 r315
  text "11" at 6316.85,6028.09 h36 r315
  text "22" at 5809.85,5741.09 h36 r315
  text "20" at 5909.85,5741.09 h36 r315
  text "18" at 6004.85,5741.09 h36 r315
  text "16" at 6101.85,5741.09 h36 r315
  text "14" at 6203.85,5741.09 h36 r315
  text "12" at 6304.85,5741.09 h36 r315
  text "10" at 6407.85,5741.09 h36 r315
  text "NC" at 6501.85,5741.09 h36 r315
  text "6" at 6607.27,5741.09 h36 r315
  text "4" at 6703.27,5741.09 h36 r315
  text "2" at 6803.27,5741.09 h36 r315
  text "24" at 5703.85,5739.09 h36 r315
  text "VDD" at 6835.11,5497.27 h36
  text "AT32F421C8T7" at 6155.03,5417.94 h120
  text "USART1_TX" at 6815.94,5400.56 h36
  text "3V3" at 4178.32,5358.52 h36
  text "3V3" at 4320.28,5358.52 h36
  text "USART1_RX" at 6815.94,5300.34 h36
  text "NC" at 4168.39,5264.94 h36
  text "GND" at 4318.22,5262.94 h36
  text "GND" at 6835.11,5199.78 h36
  text "NC" at 4167.39,5162.94 h36
  text "GND" at 4320.38,5161.12 h36
  text "SWDIO" at 4214.9,5058.94 h36
  text "GND" at 4345.22,5058.94 h36
  text "GND" at 4345.22,4962.94 h36
  text "SWCLK" at 4221.9,4958.94 h36
  text "NC" at 4181.48,4863.09 h36
  text "GND" at 4320.02,4863.09 h36
  text "VDD" at 3521.5,4854.15 h36 r270
  text "NC" at 4181.48,4759.51 h36
  text "GND" at 4320.38,4760.09 h36
  text "NRST" at 4175.16,4666.39 h36
  text "GND" at 4320.28,4666.43 h36
  text "M-BOOT0" at 3520.5,4574.15 h36 r270
  text "NC" at 4181.48,4563.09 h36
  text "GND" at 4319.66,4563.09 h36
  text "NC" at 4181.48,4461.09 h36
  text "GND" at 4320.28,4461.09 h36
  text "VDD" at 3537.58,4376.22 h36
  text "M-SWDIO" at 3525.27,4298.86 h36
  text "M-SWCLK" at 3525.27,4198.86 h36
  text "3V3" at 4065.5,4103.27 h36
  text "E5V" at 4419.2,4102.91 h36
  text "M-NRST" at 3528.43,4098.86 h36
  text "SWDIO" at 4059.18,4002.98 h36
  text "BOOT0" at 4484.65,4002.98 h36
  text "GND" at 3537.92,3998.86 h36
  text "SWCLK" at 4059.18,3902.7 h36
  text "NC" at 4386.47,3902.7 h36
  text "NRST" at 4062.34,3802.76 h36
  text "USART1_RX" at 4740.25,3802.63 h36
  text "GND" at 4065.5,3703.18 h36
  text "USART1_TX" at 4740.25,3703.03 h36
  text "26" at 5722.85,3617.09 h36 r315
  text "28" at 5819.85,3617.09 h36 r315
  text "30" at 5924.85,3617.09 h36 r315
  text "32" at 6021.85,3617.09 h36 r315
  text "34" at 6121.85,3617.09 h36 r315
  text "36" at 6222.85,3617.09 h36 r315
  text "38" at 6322.85,3617.09 h36 r315
  text "40" at 6422.85,3617.09 h36 r315
  text "44" at 6628.85,3617.09 h36 r315
  text "46" at 6729.85,3617.09 h36 r315
  text "48" at 6830.85,3617.09 h36 r315
  text "42" at 6523.85,3616.09 h36 r315
  text "25" at 5717.85,3323.09 h36 r315
  text "27" at 5814.85,3323.09 h36 r315
  text "31" at 6019.85,3323.09 h36 r315
  text "35" at 6218.85,3323.09 h36 r315
  text "37" at 6318.85,3323.09 h36 r315
  text "39" at 6419.85,3323.09 h36 r315
  text "41" at 6517.85,3323.09 h36 r315
  text "43" at 6618.85,3323.09 h36 r315
  text "45" at 6727.85,3323.09 h36 r315
  text "47" at 6829.85,3323.09 h36 r315
  text "29" at 5921.85,3321.09 h36 r315
  text "33" at 6119.85,3321.09 h36 r315
Mechanical Layer:
  lines w1 net "": 3828.44,3319 cw(c3892.75,3319.01) 3892.05,3383.31 ; 3828.44,3319 3828.44,3319 ; 3828.44,3319 ccw(c3889.36,3318.9) 3888.55,3257.99 ; 3828.46,6093.69 cw(c3892.77,6093.69) 3892.07,6158 ; 3828.46,6093.69 3828.46,6093.69 ; 3828.46,6093.69 ccw(c3889.37,6093.58) 3888.57,6032.67 ; 3846.15,6218.79 3649.37,6218.79 cw(c3649.37,6140.05) 3728.11,6140.05 3728.11,5823.39 3767.63,5823.39 3767.63,6140.05 cw(c3846.37,6140.05) 3846.15,6218.79 ; 3846.15,6218.79 3846.37,6218.79 ; 3846.15,6218.79 cw(c3846.37,6140.05) 3846.37,6218.79 ; 3846.37,6218.79 3846.37,6218.79 ; 3888.55,3257.99 3888.55,3257.99 ; 3888.55,3257.99 ccw(c3890.3,3320.65) 3892.05,3383.31 ; 3888.57,6032.67 3888.57,6032.67 ; 3888.57,6032.67 ccw(c3890.31,6095.34) 3892.07,6158 ; 3892.05,3383.31 3892.05,3383.31 ; 3892.07,6158 3892.07,6158 ; 4817.44,3756.84 cw(c4881.75,3756.84) 4881.05,3821.15 ; 4817.44,3756.84 4817.44,3756.84 ; 4817.44,3756.84 ccw(c4878.36,3756.73) 4877.55,3695.82 ; 4867.44,5656.84 cw(c4931.75,5656.84) 4931.05,5721.15 ; 4867.44,5656.84 4867.44,5656.84 ; 4867.44,5656.84 ccw(c4928.36,5656.73) 4927.55,5595.82 ; 4877.55,3695.82 4877.55,3695.82 ; 4877.55,3695.82 ccw(c4879.3,3758.49) 4881.05,3821.15 ; 4881.05,3821.15 4881.05,3821.15 ; 4927.55,5595.82 4927.55,5595.82 ; 4927.55,5595.82 ccw(c4929.3,5658.48) 4931.05,5721.15 ; 4931.05,5721.15 4931.05,5721.15 ; 6867.44,5056.84 cw(c6931.75,5056.84) 6931.05,5121.15 ; 6867.44,5056.84 6867.44,5056.84 ; 6867.44,5056.84 ccw(c6928.36,5056.73) 6927.55,4995.82 ; 6927.55,4995.82 6927.55,4995.82 ; 6927.55,4995.82 ccw(c6929.3,5058.48) 6931.05,5121.15 ; 6931.05,5121.15 6931.05,5121.15 ; 7019.44,3319 cw(c7083.75,3319.01) 7083.05,3383.31 ; 7019.44,3319 7019.44,3319 ; 7019.44,3319 ccw(c7080.36,3318.9) 7079.55,3257.99 ; 7019.44,6093.69 cw(c7083.75,6093.69) 7083.05,6158 ; 7019.44,6093.69 7019.44,6093.69 ; 7019.44,6093.69 ccw(c7080.36,6093.58) 7079.55,6032.67 ; 7079.55,3257.99 7079.55,3257.99 ; 7079.55,3257.99 ccw(c7081.3,3320.65) 7083.05,3383.31 ; 7079.55,6032.67 7079.55,6032.67 ; 7079.55,6032.67 ccw(c7081.3,6095.34) 7083.05,6158 ; 7083.05,3383.31 7083.05,3383.31 ; 7083.05,6158 7083.05,6158 ; 3649.76,3197.57 3845.39,3197.57 cw(c3845.39,3275.59) 3767.37,3275.59 3767.37,3725.33 3728.37,3725.33 3728.37,3275.65 cw(c3650.4,3275.65) 3650.4,3197.67 3649.76,3197.67 3649.76,3197.57 ; 3727.68,3797.54 3766.52,3797.54 3767.37,3798.39 3767.37,3890.39 3766.62,3891.14 3727.81,3891.14 3727.68,3797.54 ; 3728.37,4001.39 3767.37,4001.39 3767.37,5017.39 3728.37,5017.39 3728.37,4001.39 ; 3728.37,5095.39 3728.37,5745.39 3767.37,5745.39 3767.37,5095.39 3728.37,5095.39
Mech15:
  text "V_CUT" at 3318.43,6251.39 h50
  text "V_CUT" at 5417.37,6249.09 h50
